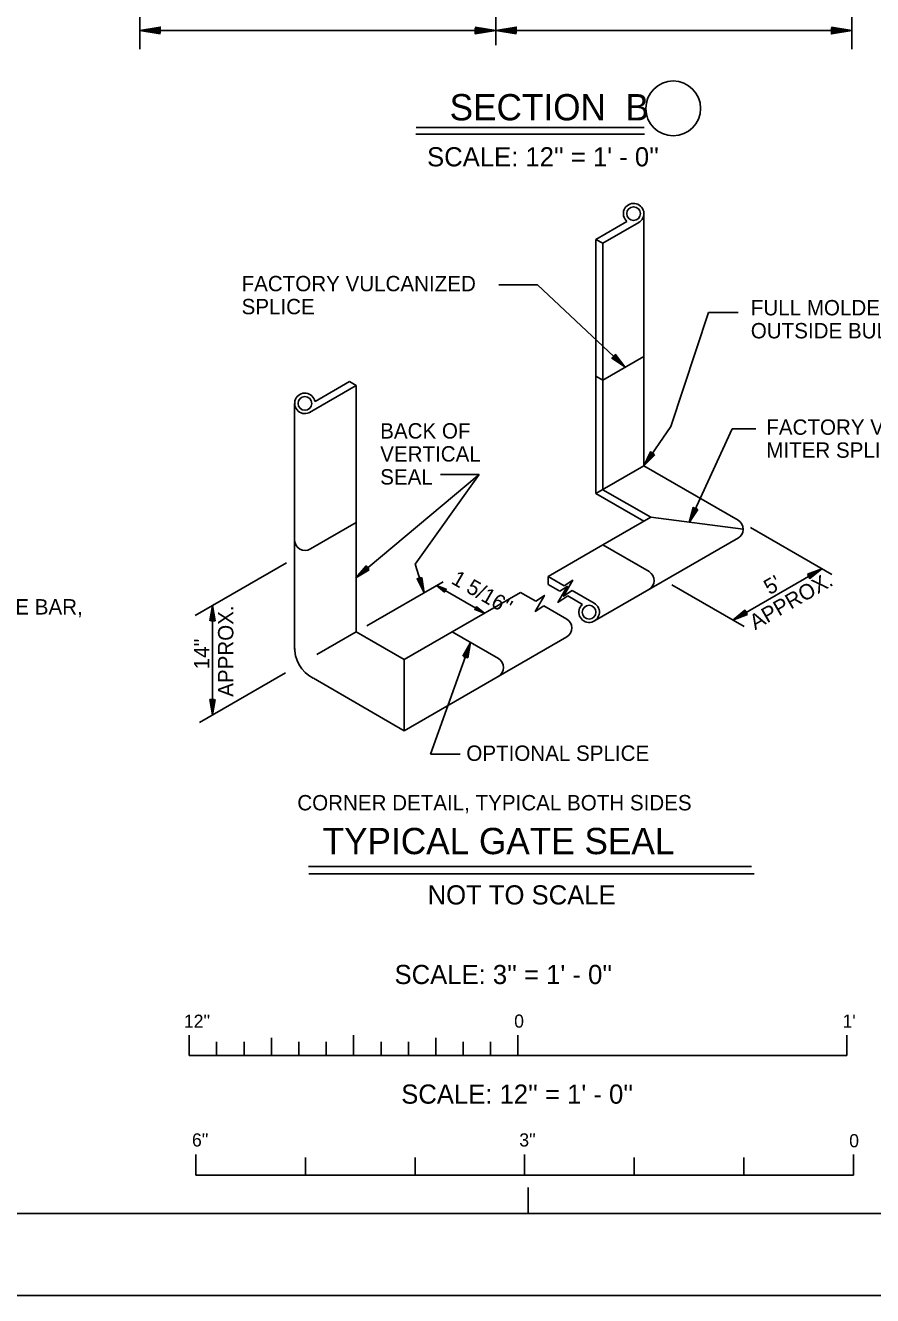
# Model space of a CAD drawing. Extents: x 22371.58 to 22374.41, y 22370.57 to 22372.4.
# Drawn here: x 22373.327 to 22373.971, y 22370.569 to 22371.536 of the extents above; entities that cross this region are included whole.
import ezdxf

# ---------------------------------------------------------------- set-up
doc = ezdxf.new("R2010")
doc.units = 0
for name, color, linetype in [('G-ANNO-SYMB', 7, 'Continuous'), ('G-ANNO-TTBL', 7, 'Continuous'), ('S-ANNO-DIMS', 7, 'Continuous'), ('S-ANNO-SYMB', 7, 'Continuous'), ('S-ANNO-TEXT', 7, 'Continuous'), ('S-GATE-SEAL', 7, 'Continuous')]:
    doc.layers.add(name, color=color, linetype=linetype)

msp = doc.modelspace()

# ---------------------------------------------------------------- linework, layer by layer
at = {"layer": 'G-ANNO-SYMB'}
msp.add_lwpolyline([(22371.57831, 22372.40278), (22374.41164, 22372.40278), (22374.41164, 22370.56945), (22371.57831, 22370.56945)], close=True, dxfattribs=at)
at = {"layer": 'G-ANNO-TTBL'}
msp.add_line((22373.70956, 22370.63195), (22373.70956, 22370.65163), dxfattribs=at)
msp.add_lwpolyline([(22371.77622, 22372.34028), (22374.19289, 22372.34028), (22374.19289, 22370.63195), (22371.77622, 22370.63195)], close=True, dxfattribs=at)
msp.add_lwpolyline([(22371.77622, 22372.34028), (22374.19289, 22372.34028), (22374.19289, 22370.63195), (22371.77622, 22370.63195)], close=True, dxfattribs=at)
at = {"layer": 'S-ANNO-DIMS'}
for p, q in [((22373.68487, 22371.95267), (22373.68487, 22371.52103)), ((22373.95571, 22371.51808), (22373.95571, 22371.83464)), ((22373.41404, 22371.78718), (22373.41404, 22371.51808)), ((22373.41404, 22371.53214), (22373.68487, 22371.53214)), ((22373.41404, 22371.53214), (22373.41404, 22371.53214)), ((22373.41837, 22371.53214), (22373.41837, 22371.53214)), ((22373.68054, 22371.53214), (22373.68054, 22371.53214)), ((22373.95571, 22371.53214), (22373.68487, 22371.53214)), ((22373.68487, 22371.53214), (22373.68487, 22371.53214)), ((22373.68921, 22371.53214), (22373.68921, 22371.53214)), ((22373.95137, 22371.53214), (22373.95137, 22371.53214)), ((22373.95571, 22371.53214), (22373.95571, 22371.53214)), ((22373.76104, 22371.37326), (22373.78461, 22371.38687)), ((22373.76625, 22371.37025), (22373.79363, 22371.38606)), ((22373.76625, 22371.37025), (22373.76104, 22371.37326)), ((22373.68715, 22371.3386), (22373.71666, 22371.3386)), ((22373.78292, 22371.27635), (22373.71666, 22371.3386)), ((22373.81802, 22371.23073), (22373.84653, 22371.3175)), ((22373.84653, 22371.3175), (22373.86924, 22371.3175)), ((22373.78056, 22371.27857), (22373.78056, 22371.27857)), ((22373.78292, 22371.27635), (22373.78292, 22371.27635)), ((22373.54328, 22371.2415), (22373.57875, 22371.26199)), ((22373.54736, 22371.24989), (22373.57354, 22371.265)), ((22373.57875, 22371.26199), (22373.57354, 22371.265)), ((22373.7975, 22371.20079), (22373.81802, 22371.23073)), ((22373.83192, 22371.15786), (22373.86454, 22371.22899)), ((22373.86454, 22371.22899), (22373.88257, 22371.22899)), ((22373.79933, 22371.20347), (22373.79933, 22371.20347)), ((22373.57845, 22371.11568), (22373.67209, 22371.19436)), ((22373.62361, 22371.12594), (22373.67209, 22371.19436)), ((22373.64277, 22371.19436), (22373.67209, 22371.19436)), ((22373.7975, 22371.20079), (22373.7975, 22371.20079)), ((22373.83192, 22371.15786), (22373.83192, 22371.15786)), ((22373.83192, 22371.15786), (22373.83192, 22371.15786)), ((22373.83328, 22371.16081), (22373.83328, 22371.16081)), ((22373.83372, 22371.16056), (22373.83372, 22371.16056)), ((22373.87851, 22371.15402), (22373.94038, 22371.1183)), ((22373.52557, 22371.12712), (22373.45618, 22371.08706)), ((22373.63027, 22371.10424), (22373.62361, 22371.12594)), ((22373.58094, 22371.11777), (22373.58094, 22371.11777)), ((22373.72457, 22371.1166), (22373.72457, 22371.1106)), ((22373.73689, 22371.10949), (22373.72458, 22371.1166)), ((22373.8652, 22371.08352), (22373.93291, 22371.12262)), ((22373.9301, 22371.12099), (22373.9301, 22371.12099)), ((22373.93291, 22371.12262), (22373.93291, 22371.12262)), ((22373.57845, 22371.11568), (22373.57845, 22371.11568)), ((22373.5868, 22371.07915), (22373.64495, 22371.11272)), ((22373.62931, 22371.10735), (22373.62931, 22371.10735)), ((22373.63974, 22371.10971), (22373.67619, 22371.08867)), ((22373.63974, 22371.10971), (22373.63974, 22371.10971)), ((22373.64161, 22371.10863), (22373.64161, 22371.10863)), ((22373.73354, 22371.10542), (22373.72457, 22371.1106)), ((22373.81882, 22371.1103), (22373.87363, 22371.07866)), ((22373.63027, 22371.10424), (22373.63027, 22371.10424)), ((22373.71529, 22371.0979), (22373.70374, 22371.10456)), ((22373.75076, 22371.09547), (22373.7396, 22371.10192)), ((22373.75975, 22371.0963), (22373.74297, 22371.10599)), ((22373.46937, 22371.01135), (22373.46937, 22371.09468)), ((22373.46937, 22371.09468), (22373.46937, 22371.09468)), ((22373.46937, 22371.09143), (22373.46937, 22371.09143)), ((22373.67432, 22371.08975), (22373.67432, 22371.08975)), ((22373.67619, 22371.08867), (22373.67619, 22371.08867)), ((22373.72136, 22371.0944), (22373.73889, 22371.08427)), ((22373.8652, 22371.08352), (22373.8652, 22371.08352)), ((22373.86802, 22371.08515), (22373.86802, 22371.08515)), ((22373.66561, 22371.06646), (22373.63525, 22370.98158)), ((22373.66452, 22371.0634), (22373.66452, 22371.0634)), ((22373.66561, 22371.06646), (22373.66561, 22371.06646)), ((22373.66743, 22371.06069), (22373.66743, 22371.06069)), ((22373.66824, 22371.06383), (22373.66824, 22371.06383)), ((22373.52495, 22371.04344), (22373.45943, 22371.00561)), ((22373.46937, 22371.0146), (22373.46937, 22371.0146)), ((22373.46937, 22371.01135), (22373.46937, 22371.01135)), ((22373.63525, 22370.98158), (22373.65783, 22370.98158))]:
    msp.add_line(p, q, dxfattribs=at)
for points in [[(22373.42962, 22371.52956), (22373.41404, 22371.53214), (22373.42962, 22371.53473), (22373.42962, 22371.53031), (22373.41837, 22371.53214), (22373.42896, 22371.53389), (22373.42896, 22371.53106), (22373.42254, 22371.53214), (22373.42829, 22371.53306), (22373.42829, 22371.53189), (22373.42687, 22371.53214)], [(22373.66929, 22371.53473), (22373.68487, 22371.53214), (22373.66929, 22371.52956), (22373.66929, 22371.53398), (22373.68054, 22371.53214), (22373.66996, 22371.53039), (22373.66996, 22371.53323), (22373.67637, 22371.53214), (22373.67062, 22371.53123), (22373.67062, 22371.53239), (22373.67204, 22371.53214)], [(22373.70046, 22371.52956), (22373.68487, 22371.53214), (22373.70046, 22371.53473), (22373.70046, 22371.53031), (22373.68921, 22371.53214), (22373.69979, 22371.53389), (22373.69979, 22371.53106), (22373.69337, 22371.53214), (22373.69912, 22371.53306), (22373.69912, 22371.53189), (22373.69771, 22371.53214)], [(22373.94012, 22371.53473), (22373.95571, 22371.53214), (22373.94012, 22371.52956), (22373.94012, 22371.53398), (22373.95137, 22371.53214), (22373.94079, 22371.53039), (22373.94079, 22371.53323), (22373.94721, 22371.53214), (22373.94146, 22371.53123), (22373.94146, 22371.53239), (22373.94287, 22371.53214)], [(22373.77574, 22371.28576), (22373.78292, 22371.27635), (22373.77308, 22371.28294), (22373.77535, 22371.28535), (22373.78056, 22371.27857), (22373.77387, 22371.28305), (22373.77533, 22371.2846), (22373.77828, 22371.28071), (22373.77466, 22371.28316), (22373.77527, 22371.2838), (22373.77591, 22371.28294)], [(22373.8057, 22371.20933), (22373.7975, 22371.20079), (22373.80251, 22371.21153), (22373.80524, 22371.20966), (22373.79933, 22371.20347), (22373.80274, 22371.21076), (22373.8045, 22371.20956), (22373.8011, 22371.20605), (22373.80298, 22371.21), (22373.80369, 22371.2095), (22373.80293, 22371.20873)], [(22373.83856, 22371.16767), (22373.83192, 22371.15786), (22373.83504, 22371.16928), (22373.83805, 22371.16791), (22373.83328, 22371.16081), (22373.83539, 22371.16857), (22373.83733, 22371.16769), (22373.83458, 22371.16365), (22373.83576, 22371.16786), (22373.83655, 22371.16749), (22373.83593, 22371.16661)], [(22373.58865, 22371.12171), (22373.57845, 22371.11568), (22373.58615, 22371.12468), (22373.58829, 22371.12215), (22373.58094, 22371.11777), (22373.58617, 22371.12388), (22373.58754, 22371.12225), (22373.58334, 22371.11978), (22373.58619, 22371.12308), (22373.58676, 22371.12241), (22373.58582, 22371.12187)], [(22373.62869, 22371.11598), (22373.63027, 22371.10424), (22373.62499, 22371.11485), (22373.62815, 22371.11581), (22373.62931, 22371.10735), (22373.62574, 22371.11455), (22373.62777, 22371.11518), (22373.6284, 22371.11033), (22373.62648, 22371.11426), (22373.62731, 22371.11451), (22373.62744, 22371.11344)], [(22373.92182, 22371.11845), (22373.93291, 22371.12262), (22373.92376, 22371.1151), (22373.9221, 22371.11796), (22373.9301, 22371.12099), (22373.92388, 22371.11589), (22373.92282, 22371.11773), (22373.92739, 22371.11943), (22373.924, 22371.11668), (22373.92356, 22371.11744), (22373.92458, 22371.1178)], [(22373.64584, 22371.1047), (22373.63974, 22371.10971), (22373.64713, 22371.10693), (22373.64603, 22371.10502), (22373.64161, 22371.10863), (22373.64663, 22371.10674), (22373.64592, 22371.10551), (22373.64341, 22371.10758), (22373.64613, 22371.10654), (22373.64584, 22371.10604), (22373.6453, 22371.1065)], [(22373.73354, 22371.10542), (22373.73916, 22371.10916), (22373.73214, 22371.09699), (22373.7396, 22371.10192)], [(22373.73689, 22371.10949), (22373.74343, 22371.11383), (22373.73641, 22371.10167), (22373.74297, 22371.10599)], [(22373.71529, 22371.0979), (22373.72183, 22371.10224), (22373.71481, 22371.09007), (22373.72136, 22371.0944)], [(22373.46743, 22371.08299), (22373.46937, 22371.09468), (22373.47131, 22371.08299), (22373.468, 22371.08299), (22373.46937, 22371.09143), (22373.47068, 22371.08349), (22373.46856, 22371.08349), (22373.46937, 22371.0883), (22373.47006, 22371.08399), (22373.46918, 22371.08399), (22373.46937, 22371.08505)], [(22373.67009, 22371.09368), (22373.67619, 22371.08867), (22373.6688, 22371.09145), (22373.6699, 22371.09336), (22373.67432, 22371.08975), (22373.6693, 22371.09164), (22373.67001, 22371.09287), (22373.67252, 22371.09079), (22373.6698, 22371.09183), (22373.67009, 22371.09233), (22373.67063, 22371.09188)], [(22373.8763, 22371.08769), (22373.8652, 22371.08352), (22373.87436, 22371.09104), (22373.87602, 22371.08818), (22373.86802, 22371.08515), (22373.87424, 22371.09025), (22373.8753, 22371.08841), (22373.87073, 22371.08671), (22373.87412, 22371.08946), (22373.87456, 22371.0887), (22373.87354, 22371.08833)], [(22373.65985, 22371.05611), (22373.66561, 22371.06646), (22373.6635, 22371.0548), (22373.66038, 22371.05592), (22373.66452, 22371.0634), (22373.66308, 22371.05548), (22373.66108, 22371.0562), (22373.66347, 22371.06046), (22373.66266, 22371.05617), (22373.66183, 22371.05646), (22373.66237, 22371.0574)], [(22373.47131, 22371.02303), (22373.46937, 22371.01135), (22373.46743, 22371.02303), (22373.47075, 22371.02303), (22373.46937, 22371.0146), (22373.46806, 22371.02253), (22373.47018, 22371.02253), (22373.46937, 22371.01772), (22373.46868, 22371.02203), (22373.46956, 22371.02203), (22373.46937, 22371.02097)]]:
    msp.add_lwpolyline(points, dxfattribs=at)
for centre in [(22373.78968, 22371.3928), (22373.53968, 22371.24844), (22373.75583, 22371.08953)]:
    msp.add_circle(centre, 0.00521, dxfattribs=at)
for centre, start, end in [((22373.78968, 22371.3928), 298.74232, 229.48989), ((22373.53968, 22371.24844), 10.68066, 302.55193), ((22373.75583, 22371.08953), 130.51788, 59.98016), ((22373.73499, 22371.0775), 299.99876, 60.08454)]:
    msp.add_arc(centre, 0.00781, start, end, dxfattribs=at)
at = {"layer": 'S-ANNO-SYMB'}
for p, q in [((22373.45172, 22370.75212), (22373.45172, 22370.76774)), ((22373.47255, 22370.75212), (22373.47255, 22370.76254)), ((22373.49338, 22370.75212), (22373.49338, 22370.76254)), ((22373.51422, 22370.75212), (22373.51422, 22370.76553)), ((22373.53505, 22370.75212), (22373.53505, 22370.76254)), ((22373.55588, 22370.75212), (22373.55588, 22370.76254)), ((22373.57672, 22370.75212), (22373.57672, 22370.76774)), ((22373.59755, 22370.75212), (22373.59755, 22370.76254)), ((22373.61838, 22370.75212), (22373.61838, 22370.76254)), ((22373.63922, 22370.75212), (22373.63922, 22370.76553)), ((22373.66005, 22370.75212), (22373.66005, 22370.76254)), ((22373.68088, 22370.75212), (22373.68088, 22370.76254)), ((22373.70172, 22370.75212), (22373.70172, 22370.76774)), ((22373.95172, 22370.75212), (22373.95172, 22370.76774)), ((22373.45172, 22370.75212), (22373.95172, 22370.75212)), ((22373.4568, 22370.6611), (22373.4568, 22370.67672)), ((22373.54013, 22370.6611), (22373.54013, 22370.67451)), ((22373.62347, 22370.6611), (22373.62347, 22370.67451)), ((22373.7068, 22370.6611), (22373.7068, 22370.67672)), ((22373.79013, 22370.6611), (22373.79013, 22370.67451)), ((22373.87347, 22370.6611), (22373.87347, 22370.67451)), ((22373.9568, 22370.6611), (22373.9568, 22370.67672)), ((22373.4568, 22370.6611), (22373.9568, 22370.6611))]:
    msp.add_line(p, q, dxfattribs=at)
at = {"layer": 'S-ANNO-TEXT'}
for p, q in [((22373.62421, 22371.45844), (22373.79764, 22371.45844)), ((22373.62393, 22371.45324), (22373.79791, 22371.45324)), ((22373.54236, 22370.89591), (22373.87939, 22370.89591)), ((22373.54273, 22370.89041), (22373.88126, 22370.89041))]:
    msp.add_line(p, q, dxfattribs=at)
msp.add_circle((22373.8198, 22371.47293), 0.02083, dxfattribs=at)
at = {"layer": 'S-GATE-SEAL'}
for p, q in [((22373.7975, 22371.20079), (22373.7975, 22371.3928)), ((22373.76104, 22371.17974), (22373.76104, 22371.37326)), ((22373.76625, 22371.18275), (22373.76625, 22371.37025)), ((22373.76625, 22371.26607), (22373.7975, 22371.28412)), ((22373.57875, 22371.07449), (22373.57875, 22371.26199)), ((22373.76625, 22371.26607), (22373.76104, 22371.26908)), ((22373.53187, 22371.06114), (22373.53187, 22371.24844)), ((22373.76104, 22371.17974), (22373.7975, 22371.20079)), ((22373.86912, 22371.15945), (22373.7975, 22371.20079)), ((22373.7975, 22371.1587), (22373.76104, 22371.17974)), ((22373.8027, 22371.16171), (22373.76625, 22371.18275)), ((22373.54389, 22371.1377), (22373.57875, 22371.15782)), ((22373.76625, 22371.14066), (22373.8027, 22371.16171)), ((22373.8027, 22371.16171), (22373.87303, 22371.1527)), ((22373.76004, 22371.08295), (22373.86937, 22371.14607)), ((22373.72457, 22371.1166), (22373.76624, 22371.14066)), ((22373.80141, 22371.12036), (22373.76625, 22371.14066)), ((22373.65166, 22371.0745), (22373.70374, 22371.10456)), ((22373.5488, 22371.0572), (22373.57875, 22371.07449)), ((22373.6152, 22371.05345), (22373.57875, 22371.07449)), ((22373.6152, 22371.05345), (22373.65166, 22371.0745)), ((22373.6152, 22370.99932), (22373.73894, 22371.07076)), ((22373.68681, 22371.05421), (22373.65166, 22371.0745)), ((22373.6152, 22371.05345), (22373.6152, 22370.99932)), ((22373.6152, 22370.99932), (22373.54611, 22371.0392))]:
    msp.add_line(p, q, dxfattribs=at)
for centre, radius, start, end in [((22373.86522, 22371.15269), 0.00781, 297.56444, 59.98016), ((22373.53968, 22371.14428), 0.00781, 180, 302.58836), ((22373.79751, 22371.1136), 0.00781, 297.56444, 59.98016), ((22373.55805, 22371.06254), 0.02622, 176.92499, 242.74354), ((22373.68291, 22371.04744), 0.00781, 299.99876, 60.08454)]:
    msp.add_arc(centre, radius, start, end, dxfattribs=at)

# ---------------------------------------------------------------- texts
at = {"layer": 'S-ANNO-DIMS'}
for s, rotation, p in [("1 5/16''", 330.00646, (22373.65019, 22371.1118)), ('APPROX.', 30.00148, (22373.88214, 22371.07571)), ("5'", 30.00148, (22373.89304, 22371.10235)), ('APPROX.', 90, (22373.48528, 22371.02513)), ("14''", 90, (22373.46702, 22371.04603))]:
    msp.add_text(s, height=0.011698, rotation=rotation, dxfattribs=at).set_placement(p)
for s, p in [('CLOSURE BAR,', (22373.25423, 22371.08775)), ('OPTIONAL SPLICE', (22373.66244, 22370.97637)), ('CORNER DETAIL, TYPICAL BOTH SIDES', (22373.5339, 22370.93869))]:
    msp.add_text(s, height=0.0116979, dxfattribs=at).set_placement(p)
at = {"layer": 'S-ANNO-SYMB'}
for s, height, p in [("SCALE: 3'' = 1' - 0''", 0.0145831, (22373.60784, 22370.80652)), ("12''", 0.01, (22373.44764, 22370.77324)), ('0', 0.01, (22373.69883, 22370.77334)), ("1'", 0.01, (22373.94857, 22370.77334)), ("SCALE: 12'' = 1' - 0''", 0.0145829, (22373.61293, 22370.71549)), ("6''", 0.01, (22373.45379, 22370.68291)), ("3''", 0.01, (22373.70273, 22370.68291)), ('0', 0.01, (22373.95365, 22370.68232))]:
    msp.add_text(s, height=height, dxfattribs=at).set_placement(p)
at = {"layer": 'S-ANNO-TEXT'}
for s, height, p in [('SECTION  B', 0.02, (22373.64974, 22371.4638)), ('FACTORY VULCANIZED', 0.0116979, (22373.4915, 22371.33374)), ('SPLICE', 0.011698, (22373.4915, 22371.31624)), ('FULL MOLDED VERTICAL', 0.0116979, (22373.8788, 22371.31539)), ('OUTSIDE BULB CORNER', 0.0116979, (22373.8788, 22371.29789)), ('BACK OF', 0.011698, (22373.59693, 22371.22166)), ('FACTORY VULCANIZED', 0.0116979, (22373.89057, 22371.22452)), ('VERTICAL', 0.011698, (22373.59693, 22371.20416)), ('MITER SPLICE JOINT', 0.0116979, (22373.89057, 22371.20702)), ('SEAL', 0.011698, (22373.59693, 22371.18666)), ('TYPICAL GATE SEAL', 0.02, (22373.55314, 22370.90537))]:
    msp.add_text(s, height=height, dxfattribs=at).set_placement(p)
at = {"layer": 'S-GATE-SEAL'}
for s, height, p in [("SCALE: 12'' = 1' - 0''", 0.0145829, (22373.63259, 22371.42878)), ('NOT TO SCALE', 0.0145833, (22373.63299, 22370.8671))]:
    msp.add_text(s, height=height, dxfattribs=at).set_placement(p)

doc.saveas('drawing.dxf')
